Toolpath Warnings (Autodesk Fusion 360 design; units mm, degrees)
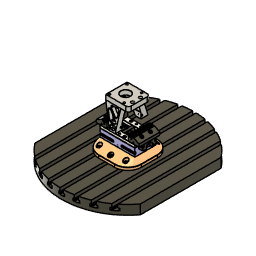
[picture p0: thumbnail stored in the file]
parameter "minJawOpening" = -31.6941 comment "Minimum Jaw Opening"
parameter "maxJawOpening" = 0 comment "Maximum Jaw Opening"
parameter "stockX" = 165.1 comment "Stock in X"
parameter "stockY" = 114.3 comment "Stock in Y"
parameter "stockZ" = 120.65 comment "Stock in Z"
base_feature "Base Feature1" OffsetX 0 OffsetY 0 OffsetZ 0 AngleZ 0
base_feature "Base Feature1"
base_feature "Base Feature1"
base_feature "Base Feature1"
base_feature "Base Feature1"
base_feature "Base Feature1"
base_feature "Base Feature1"
base_feature "Base Feature1"
base_feature "Base Feature1" OffsetX 0 OffsetY 0 OffsetZ 0 AngleZ 0 OffsetX 0 OffsetY 0 OffsetZ 0 AngleZ 0 OffsetX 0 OffsetY 0 OffsetZ 0 AngleZ 0 OffsetX 0 OffsetY 0 OffsetZ 0 AngleZ 0 OffsetX 0 OffsetY 0 OffsetZ 0 AngleZ 0
base_feature "Base Feature1" OffsetX 0 OffsetY 0 OffsetZ 0 AngleZ 0 OffsetX 0 OffsetY 0 OffsetZ 0 AngleZ 0 OffsetX 0 OffsetY 0 OffsetZ 0 AngleZ 0 OffsetX 0 OffsetY 0 OffsetZ 0 AngleZ 0 OffsetX 0 OffsetY 0 OffsetZ 0 AngleZ 0
base_feature "Base Feature1"
base_feature "Base Feature1"
base_feature "Base Feature1"
base_feature "Base Feature1"
as_built_joint "As-built1"
as_built_joint "As-built1"
as_built_joint "As-built1"
as_built_joint "As-built1"
as_built_joint "As-built1"
as_built_joint "As-built1"
joint "Assemble1" alignAngle 0 alignOffsetX 0 alignOffsetY 0 alignOffsetZ 0
as_built_joint "As-built3"
as_built_joint "As-built5"
as_built_joint "As-built6" OffsetX 0 OffsetY 0 OffsetZ 0 AngleZ 0
as_built_joint "As-built7" OffsetX 0 OffsetY 0 OffsetZ 0 AngleZ 0
work_plane "WorkPlane1" AlongDistance 0
joint_origin "JointOrigin1" OffsetX 0 OffsetY 0 OffsetZ 75.463 AngleZ 0
sketch "Sketch1" plane through (0, 0, 0) normal (0, 1, 0) x axis (1, 0, 0)
  line L1 (-15.24, -30.48) -> (-180.34, -30.48)
  line L2 (-15.24, 83.82) -> (-15.24, -30.48)
  line L3 (-180.34, 83.82) -> (-15.24, 83.82)
  line L4 (-180.34, -30.48) -> (-180.34, 83.82)
  point P2 (-180.34, -30.48)
  point P5 (-180.34, 83.82)
  point P3 (-15.24, -30.48)
  horizontal L1
  vertical L2
  horizontal L3
  vertical L4
  dimension "d111" distance P2 P5 = 114.3 (= "stockY")
  dimension "d112" distance P2 P3 = 165.1 (= "stockX")
  dimension "d318" OffsetX = 0
  dimension "d319" OffsetY = 0
  dimension "d320" OffsetZ = 0
  dimension "d321" AngleZ = 0
extrude "Extrude1" new body sketch "Sketch1" along normal blind 120.65 (= "stockZ")
joint_origin "JointOrigin1" OffsetX 0 OffsetY 0 OffsetZ 0 AngleZ 0
joint "Assemble2" alignAngle 0 alignOffsetX 0 alignOffsetY 0 alignOffsetZ 0
motion_link "MotionLink1" Value1 10.0076 Value2 10.0076
joint "Assemble3" alignAngle 180 alignOffsetX 0 alignOffsetY 0 alignOffsetZ 101.6 (= "stockY - 0.5 in")
base_feature "Base Feature1"
base_feature "Base Feature1"
joint "Assemble4" alignAngle 180 alignOffsetX 0 alignOffsetY 0 alignOffsetZ 0
joint "Assemble5" alignAngle 0 alignOffsetX 0 alignOffsetY 0 alignOffsetZ 0
base_feature "Base Feature1"
joint "Assemble6" alignAngle -90 alignOffsetX 0 alignOffsetY 0 alignOffsetZ 0
base_feature "Base Feature1"
joint_origin "JointOrigin1" OffsetX 0 named "d201_1" OffsetY 0 named "d202_1" OffsetZ 0 named "d203_1" AngleZ 0 named "d204_1"
base_feature "Base Feature1"
joint_origin "JointOrigin1" OffsetX 0 named "d201_2" OffsetY 0 named "d202_2" OffsetZ 0 named "d203_2" AngleZ 0 named "d204_2"
joint "Assemble7" alignAngle -90 alignOffsetX 0 alignOffsetY 0 alignOffsetZ 0
joint "Assemble8" alignAngle -90 alignOffsetX 0 alignOffsetY 0 alignOffsetZ 0
copy_paste "CutPaste1"
copy_paste "CutPaste2"
copy_paste "CutPaste1"
copy_paste "CutPaste2"
copy_paste "CutPaste3"
base_feature "Base Feature1"
joint_origin "JointOrigin1" OffsetX 0 named "d201_2_1" OffsetY 0 named "d202_2_1" OffsetZ 0 named "d203_2_1" AngleZ 0 named "d204_2_1"
joint_origin "JointOrigin2" OffsetX 0 named "d213_1" OffsetY 0 named "d214_1" OffsetZ 0 named "d215_1" AngleZ 0 named "d216_1"
base_feature "Base Feature1"
joint_origin "JointOrigin1" OffsetX 0 named "d201_3" OffsetY 0 named "d202_3" OffsetZ 0 named "d203_3" AngleZ 0 named "d204_3"
base_feature "Base Feature1"
joint_origin "JointOrigin1" OffsetX 0 named "d201_1_1" OffsetY 0 named "d202_1_1" OffsetZ 0 named "d203_1_1" AngleZ 0 named "d204_1_1"
joint_origin "JointOrigin2" OffsetX 0 named "d225_1" OffsetY 0 named "d226_1" OffsetZ 0 named "d227_1" AngleZ 0 named "d228_1"
joint "Assemble9" alignAngle 90 alignOffsetX 0 alignOffsetY 0 alignOffsetZ 0
joint "Assemble10" alignAngle 90 alignOffsetX 0 alignOffsetY 0 alignOffsetZ 0
joint "Assemble11" alignAngle 90 alignOffsetX 0 alignOffsetY 0 alignOffsetZ 0
copy_paste "CutPaste4"
copy_paste "CutPaste5"
copy_paste "CutPaste6"
base_feature "Base Feature1" OffsetX 0 OffsetY 0 OffsetZ 0 AngleZ 0 bodies "Table"
joint_origin "JointOrigin1" OffsetX 0 named "d149_1" OffsetY 0 named "d150_1" OffsetZ 0 named "d151_1" AngleZ 0 named "d152_1"
joint_origin "JointOrigin2" OffsetX 0 named "d153_1" OffsetY 0 named "d154_1" OffsetZ 0 named "d155_1" AngleZ 0 named "d156_1"
joint_origin "JointOrigin3" OffsetX 0 named "d157_1" OffsetY 0 named "d158_1" OffsetZ 0 named "d159_1" AngleZ 0 named "d160_1"
joint_origin "JointOrigin4" OffsetX 0 named "d161_1" OffsetY 0 named "d162_1" OffsetZ 0 named "d163_1" AngleZ 0 named "d164_1"
joint_origin "JointOrigin5" OffsetX 0 named "d165_1" OffsetY 0 named "d166_1" OffsetZ 0 named "d167_1" AngleZ 0 named "d168_1"
joint_origin "JointOrigin6" OffsetX 0 named "d169_1" OffsetY 0 named "d170_1" OffsetZ 0 named "d171_1" AngleZ 0 named "d172_1"
joint_origin "JointOrigin7" OffsetX 0 named "d173_1" OffsetY 0 named "d174_1" OffsetZ 0 named "d175_1" AngleZ 0 named "d176_1"
joint_origin "JointOrigin8" OffsetX 0 named "d177_1" OffsetY 0 named "d178_1" OffsetZ 0 named "d179_1" AngleZ 0 named "d180_1"
joint_origin "JointOrigin9" OffsetX 0 named "d181_1" OffsetY 0 named "d182_1" OffsetZ 0 named "d183_1" AngleZ 0 named "d184_1"
joint_origin "JointOrigin10" OffsetX 0 named "d185_1" OffsetY 0 named "d186_1" OffsetZ 0 named "d187_1" AngleZ 0 named "d188_1"
joint_origin "JointOrigin11" OffsetX 0 named "d189_1" OffsetY 0 named "d190_1" OffsetZ 0 named "d191_1" AngleZ 0 named "d192_1"
joint_origin "JointOrigin12" OffsetX 0 named "d193_1" OffsetY 0 named "d194_1" OffsetZ 0 named "d195_1" AngleZ 0 named "d196_1"
joint_origin "JointOrigin13" OffsetX 0 named "d197_1" OffsetY 0 named "d198_1" OffsetZ 0 named "d199_1" AngleZ 0 named "d200_1"
joint_origin "JointOrigin14" OffsetX 0 named "d201_4" OffsetY 0 named "d202_4" OffsetZ 0 named "d203_4" AngleZ 0 named "d204_4"
joint_origin "JointOrigin15" OffsetX 0 named "d205_1" OffsetY 0 named "d206_1" OffsetZ 0 named "d207_1" AngleZ 0 named "d208_1"
joint_origin "JointOrigin16" OffsetX 0 named "d209_1" OffsetY 0 named "d210_1" OffsetZ 0 named "d211_1" AngleZ 0 named "d212_1"
joint_origin "JointOrigin17" OffsetX 0 named "d213_2" OffsetY 0 named "d214_2" OffsetZ 0 named "d215_2" AngleZ 0 named "d216_2"
joint_origin "JointOrigin18" OffsetX 0 named "d217_1" OffsetY 0 named "d218_1" OffsetZ 0 named "d219_1" AngleZ 0 named "d220_1"
as_built_joint "As-built1"
joint "Assemble12" alignAngle 90 alignOffsetX 0 alignOffsetY 0 alignOffsetZ 38.1 (= "4 in - 2.5 in")
copy_paste "CutPaste1"
sketch "Sketch1" plane through (0, 0, 0) normal (0, -1, 0) x axis (1, 0, 0)
  line L1 (-50, 82.4998) -> (50, 82.4998)
  line L2 (-50, -82.4998) -> (-50, 82.4998)
  line L3 (50, -82.4998) -> (-50, -82.4998)
  line L4 (50, 82.4998) -> (50, -82.4998)
  line L5 (-50, -82.4998) -> (50, 82.4998)
  line L6 (50, -82.4998) -> (-50, 82.4998)
  point P6 (0, 0)
  point P1 (0, 0)
  point P2 (50, 82.4998)
  point P7 (50, 82.4998)
  perpendicular L1 L2
  parallel L1 L3
  parallel L2 L4
  horizontal L1
  coincident L5 P6
  coincident L6 P6
  coincident P1 P6
  coincident P2 P7
  dimension "d358" OffsetX = 0
  dimension "d359" OffsetY = 0
  dimension "d360" OffsetZ = 0
  dimension "d361" AngleZ = 0
extrude "Extrude1" new body sketch "Sketch1" profile of L1 L2 L3 L4 along normal blind 3.81
sketch "Sketch2" plane through (0, -38.1, 0) normal (0, 1, 0) x axis (-1, 0, 0)
  line L1 (-101.6, 101.6) -> (101.6, 101.6)
  line L2 (-101.6, -101.6) -> (-101.6, 101.6)
  line L3 (101.6, -101.6) -> (-101.6, -101.6)
  line L4 (101.6, 101.6) -> (101.6, -101.6)
  line L5 (-101.6, -101.6) -> (101.6, 101.6)
  line L6 (101.6, -101.6) -> (-101.6, 101.6)
  point P6 (0, 0)
  point P1 (0, 0)
  point P2 (101.6, 101.6)
  point P3 (-101.6, 101.6)
  perpendicular L1 L2
  parallel L1 L3
  parallel L2 L4
  horizontal L1
  coincident L5 P6
  coincident L6 P6
  coincident P1 P6
  equal L1 L4
  dimension "d287" distance P2 P3 = 203.2
extrude "Extrude2" new body sketch "Sketch2" profile of L1 L2 L3 L4 along normal blind 12.7
fillet "Fillet1" radius 63.5
fillet "Fillet2" radius 1.27
loft "Loft1"
sketch "Sketch3" plane through (0, -38.1, 0) normal (0, -1, 0) x axis (1, 0, 0)
  circle C1 centre (0, 0) radius 28.575
  point P1 (0, 0)
  point P2 (0, 0)
  coincident P1 P2
  dimension "d292" diameter C1 = 57.15
extrude "Extrude3" add sketch "Sketch3" along normal blind 6.35
as_built_joint "As-built8"
as_built_joint "As-built9"
sketch "Sketch2" plane through (0, 0, 0) normal (0, 0, 1) x axis (1, 0, 0)
  line L1 (482.6, 147.0957) -> (179.3748, 147.0957)
  line L2 (482.6, 58.1957) -> (482.6, 147.0957)
  line L3 (444.5, 58.1957) -> (482.6, 58.1957)
  line L4 (444.5, 80.4207) -> (444.5, 58.1957)
  line L5 (333.375, 80.4207) -> (444.5, 80.4207)
  line L6 (333.375, 110.2657) -> (333.375, 80.4207)
  line L7 (320.675, 110.2657) -> (333.375, 110.2657)
  line L8 (320.675, 115.3457) -> (320.675, 110.2657)
  line L9 (307.34, 115.3457) -> (320.675, 115.3457)
  line L10 (305.054, 124.7183) -> (307.34, 115.3457)
  line L11 (264.414, 124.7183) -> (305.054, 124.7183)
  line L12 (264.414, 128.4267) -> (264.414, 124.7183)
  line L13 (261.1628, 128.4267) -> (264.414, 128.4267)
  line L14 (261.1628, 124.7183) -> (261.1628, 128.4267)
  line L15 (255.5748, 124.7183) -> (261.1628, 124.7183)
  line L16 (255.5748, 127.1186) -> (255.5748, 124.7183)
  line L17 (217.4748, 127.1186) -> (255.5748, 127.1186)
  line L18 (217.4748, 140.7457) -> (217.4748, 127.1186)
  line L19 (179.3748, 140.7457) -> (217.4748, 140.7457)
  line L20 (179.3748, 147.0957) -> (179.3748, 140.7457)
  point P2 (179.3748, 147.0957)
  point P22 (179.3748, 147.0957)
  point P3 (482.6, 147.0957)
  point P4 (482.6, 58.1957)
  point P14 (264.414, 128.4267)
  point P15 (261.1628, 128.4267)
  point P5 (444.5, 58.1957)
  point P6 (444.5, 80.4207)
  point P7 (333.375, 80.4207)
  point P8 (333.375, 110.2657)
  point P9 (320.675, 110.2657)
  point P10 (320.675, 115.3457)
  point P11 (307.34, 115.3457)
  point P12 (305.054, 124.7183)
  point P13 (264.414, 124.7183)
  point P16 (261.1628, 124.7183)
  point P17 (255.5748, 124.7183)
  point P20 (217.4748, 140.7457)
  point P21 (179.3748, 140.7457)
  point P18 (255.5748, 127.1186)
  point P19 (217.4748, 127.1186)
  horizontal L1
  perpendicular L1 L2
  perpendicular L2 L3
  perpendicular L1 L4
  perpendicular L2 L5
  perpendicular L1 L6
  perpendicular L6 L7
  perpendicular L7 L8
  perpendicular L8 L9
  perpendicular L8 L11
  perpendicular L11 L12
  perpendicular L12 L13
  perpendicular L13 L14
  perpendicular L14 L15
  perpendicular L15 L16
  collinear L11 L15
  perpendicular L17 L18
  perpendicular L18 L19
  perpendicular L19 L20
  coincident P2 P22
  dimension "d295" distance P3 P4 = 88.9
  dimension "d296" distance L1 L5 = 66.675 (= "( 5.25 / 2 ) * 1 in")
  dimension "d297" distance L1 L7 = 36.83 (= "( 2.9 / 2 ) * 1 in")
  dimension "d298" distance L1 L9 = 31.75 (= "( 2.5 / 2 ) * 1 in")
  dimension "d299" distance L1 L11 = 22.3774 (= "( 1.762 / 2 ) * 1 in")
  dimension "d300" distance L1 L13 = 18.669 (= "( 1.47 / 2 ) * 1 in")
  dimension "d301" distance L1 L17 = 19.9771 (= "( 1.573 / 2 ) * 1 in")
  dimension "d302" distance P14 P15 = 3.2512
  dimension "d303" distance P4 P5 = 38.1
  dimension "d304" distance P6 P7 = 111.125
  dimension "d305" distance P8 P9 = 12.7
  dimension "d306" distance P10 P11 = 13.335
  dimension "d307" distance P11 P12 = 2.286
  dimension "d308" distance P12 P13 = 40.64
  dimension "d309" distance P16 P17 = 5.588
  dimension "d310" distance L1 L19 = 6.35
  dimension "d311" distance P20 P21 = 38.1
  dimension "d312" distance P18 P19 = 38.1
revolve "Revolve1" sketch "Sketch2" AlongAngle 360
component_from_bodies "Body->Comp"
joint "Assemble13" alignAngle 180 alignOffsetX 0 alignOffsetY -15.24 alignOffsetZ -12.7
copy_paste "CutPaste2"
copy_paste "CutPaste3"
sketch "Sketch4" plane through (0, -38.1, 0) normal (0, -1, 0) x axis (1, 0, 0)
  line L1 (-191.6377, 250) -> (191.6377, 250)
  line L2 (191.6377, -250) -> (-191.6377, -250)
  line L3 (310.1389, -55.126) -> (9.652, -55.126)
  line L4 (9.652, -70.874) -> (306.9232, -70.874)
  circle C1 centre (-73.025, 63) radius 6.6675
  circle C2 centre (73.025, 63) radius 6.6675
  circle C3 centre (82.55, 0) radius 6.6675
  circle C4 centre (-82.55, 0) radius 6.6675
  circle C5 centre (-73.025, -63) radius 6.6675
  circle C6 centre (73.025, -63) radius 6.6675
  arc A1 centre (0, 0) radius 315 clockwise from (191.6377, 250) to (191.6377, -250)
  arc A2 centre (0, 0) radius 315 clockwise from (-191.6377, -250) to (-191.6377, 250)
  circle C7 centre (59.8029, -16.0241) radius 6.7437
  circle C8 centre (-16.0241, -59.8029) radius 6.7437
  circle C9 centre (-43.7787, -43.7787) radius 6.7437
  circle C10 centre (-43.7787, 43.7787) radius 6.7437
  circle C11 centre (-16.0241, 59.8029) radius 6.7437
  circle C12 centre (59.8029, 16.0241) radius 6.7437
  circle C13 centre (0, 0) radius 0.4391
  arc A3 centre (-60.96, 63) radius 7.874 clockwise from (-60.96, 70.874) to (-60.96, 55.126)
  arc A4 centre (9.652, 63) radius 7.874 clockwise from (9.652, 55.126) to (9.652, 70.874)
  arc A5 centre (9.652, -63) radius 7.874 clockwise from (9.652, -70.874) to (9.652, -55.126)
  arc A6 centre (0, 0) radius 315 clockwise from (310.1389, -55.126) to (306.9232, -70.874)
  arc A7 centre (-60.96, -63) radius 7.874 clockwise from (-60.96, -55.126) to (-60.96, -70.874)
  arc A8 centre (-42.672, 0) radius 7.874 clockwise from (-42.672, 7.874) to (-42.672, -7.874)
  arc A9 centre (80.01, 0) radius 7.874 clockwise from (80.01, -7.874) to (80.01, 7.874)
  point P3 (73.025, 63)
  point P24 (9.652, 63)
  point P2 (-73.025, 63)
  point P7 (73.025, -63)
  point P27 (9.652, -63)
  point P6 (-73.025, -63)
  point P4 (82.55, 0)
  point P39 (80.01, 0)
  point P5 (-82.55, 0)
  point P36 (-42.672, 0)
  point P1 (0, 0)
  equal C5 C6
  equal C4 C5
  equal C1 C4
  equal C1 C2
  equal C2 C3
  horizontal P3 P24
  horizontal P2 P3
  horizontal P7 P27
  horizontal P6 P7
  vertical P2 P6
  vertical P3 P7
  horizontal P4 P39
  horizontal P5 P36
  dimension "d342" diameter C1 = 13.335
  dimension "d343" distance P1 P7 = 73.025
  dimension "d344" distance P1 P6 = 73.025 (= "d343")
  dimension "d346" distance P1 P5 = 82.55
  dimension "d347" distance P1 P4 = 82.55 (= "d346")
extrude "Extrude4" cut sketch "Sketch4" profile of C1 C2 C3 C4 C5 C6 A9 no distance stored
work_plane "WorkPlane1" AlongDistance -6.35
sketch "Sketch5" plane through (0, -31.75, 0) normal (0, -1, 0) x axis (1, 0, 0)
  circle C1 centre (73.025, 63) radius 9.8425
  circle C2 centre (73.025, 63) radius 6.6675
  circle C3 centre (82.55, 0) radius 9.8425
  circle C4 centre (73.025, -63) radius 9.8425
  circle C5 centre (-73.025, -63) radius 9.8425
  circle C6 centre (-82.55, 0) radius 9.8425
  circle C7 centre (-73.025, 63) radius 9.8425
  circle C8 centre (-73.025, 63) radius 6.6675
  circle C9 centre (-82.55, 0) radius 6.6675
  circle C10 centre (-73.025, -63) radius 6.6675
  circle C11 centre (73.025, -63) radius 6.6675
  circle C12 centre (82.55, 0) radius 6.6675
  concentric C1 C2
  equal C6 C7
  equal C5 C6
  equal C4 C5
  equal C3 C4
  equal C1 C3
  concentric C7 C8
  concentric C6 C9
  concentric C5 C10
  concentric C4 C11
  concentric C3 C12
  dimension "d349" diameter C1 = 19.685
extrude "Extrude5" cut sketch "Sketch5" no distance stored
chamfer "Chamfer1" distance 0.762
chamfer "Chamfer2" distance 0.762
base_feature "Base Feature1" OffsetX 0 OffsetY 0 OffsetZ 0 AngleZ 0
joint "Assemble14" alignAngle 0 alignOffsetX 0 alignOffsetY 0 alignOffsetZ 0
base_feature "Base Feature1" OffsetX 0 named "d354_1" OffsetY 0 named "d355_1" OffsetZ 0 named "d356_1" AngleZ 0 named "d357_1"
joint_origin "JointOrigin2" OffsetX 0 named "d366_1" OffsetY 0 named "d367_1" OffsetZ 0 named "d368_1" AngleZ 0 named "d369_1"
base_feature "Base Feature1" OffsetX 0 named "d354_2" OffsetY 0 named "d355_2" OffsetZ 0 named "d356_2" AngleZ 0 named "d357_2"
joint_origin "JointOrigin2" OffsetX 0 named "d366_2" OffsetY 0 named "d367_2" OffsetZ 0 named "d368_2" AngleZ 0 named "d369_2"
base_feature "Base Feature1" OffsetX 0 named "d354_3" OffsetY 0 named "d355_3" OffsetZ 0 named "d356_3" AngleZ 0 named "d357_3"
joint_origin "JointOrigin2" OffsetX 0 named "d366_3" OffsetY 0 named "d367_3" OffsetZ 0 named "d368_3" AngleZ 0 named "d369_3"
base_feature "Base Feature1" OffsetX 0 named "d354_4" OffsetY 0 named "d355_4" OffsetZ 0 named "d356_4" AngleZ 0 named "d357_4"
joint_origin "JointOrigin2" OffsetX 0 named "d366_4" OffsetY 0 named "d367_4" OffsetZ 0 named "d368_4" AngleZ 0 named "d369_4"
base_feature "Base Feature1" OffsetX 0 named "d354_5" OffsetY 0 named "d355_5" OffsetZ 0 named "d356_5" AngleZ 0 named "d357_5"
joint_origin "JointOrigin2" OffsetX 0 named "d366_5" OffsetY 0 named "d367_5" OffsetZ 0 named "d368_5" AngleZ 0 named "d369_5"
joint "Assemble15" alignAngle 0 alignOffsetX 0 alignOffsetY 0 alignOffsetZ 0
joint "Assemble16" alignAngle 0 alignOffsetX 0 alignOffsetY 0 alignOffsetZ 0
joint "Assemble17" alignAngle 0 alignOffsetX 0 alignOffsetY 0 alignOffsetZ 0
joint "Assemble18" alignAngle 0 alignOffsetX 0 alignOffsetY 0 alignOffsetZ 0
joint "Assemble19" alignAngle 0 alignOffsetX 0 alignOffsetY 0 alignOffsetZ 0
copy_paste "CutPaste4"
copy_paste "CutPaste5"
copy_paste "CutPaste6"
copy_paste "CutPaste7"
copy_paste "CutPaste8"
copy_paste "CutPaste9"
sketch "Sketch2" plane through (0, 0, 0) normal (0, -1, 0) x axis (1, 0, 0)
  line L1 (-50, 82.4998) -> (50, 82.4998)
  line L2 (-50, -82.4998) -> (-50, 82.4998)
  line L3 (50, -82.4998) -> (-50, -82.4998)
  line L4 (50, 82.4998) -> (50, -82.4998)
  line L5 (-50, -82.4998) -> (50, 82.4998)
  line L6 (50, -82.4998) -> (-50, 82.4998)
  point P6 (0, 0)
  point P1 (0, 0)
  point P2 (50, 82.4998)
  point P7 (50, 82.4998)
  perpendicular L1 L2
  parallel L1 L3
  parallel L2 L4
  horizontal L1
  coincident L5 P6
  coincident L6 P6
  coincident P1 P6
  coincident P2 P7
extrude "Extrude2" new body sketch "Sketch2" profile of L1 L2 L3 L4 along normal blind 2.54
fillet "Fillet2" radius 1.27
as_built_joint "As-built10"
remove_instance "RemoveInstance18"
base_feature "Base Feature1"
position "Position32"
joint "Assemble21" OffsetX 0 OffsetY 0 OffsetZ 0 AngleZ 0 alignAngle 180 alignOffsetX 0 alignOffsetY 0 alignOffsetZ -114.0572
as_built_joint "As-built12"
sketch "Side Containment" plane through (82.55, 0, 6.35) normal (1, 0, 0) x axis (0, 1, 0)
  line L1 (75.463, -63.5) -> (75.463, 50.8)
  line L2 (196.113, -63.5) -> (75.463, -63.5)
  line L3 (196.113, 50.8) -> (196.113, -63.5)
  line L4 (75.463, 50.8) -> (196.113, 50.8)
  line L5 (79.5905, 95.25) -> (231.9905, 95.25)
  line L6 (79.5905, 39.37) -> (79.5905, 95.25)
  line L7 (55.0926, 39.37) -> (79.5905, 39.37)
  line L8 (55.0926, -52.07) -> (55.0926, 39.37)
  line L9 (79.5905, -52.07) -> (55.0926, -52.07)
  line L10 (79.5905, -107.95) -> (79.5905, -52.07)
  line L11 (231.9905, -107.95) -> (79.5905, -107.95)
  line L12 (231.9905, 95.25) -> (231.9905, -107.95)
  line L13 (48.4465, 0) -> (48.4465, -12.7)
  line L14 (231.9905, -6.35) -> (48.4465, -6.35)
  line L15 (50.063, 44.45) -> (75.463, 44.45)
  line L16 (50.0126, 75.3878) -> (50.0126, -88.0878)
  line L17 (77.0505, 51.054) -> (77.0505, 63.246)
  point P16 (48.4465, -6.35)
  point P17 (231.9905, -6.35)
  point P6 (231.9905, 95.25)
  point P13 (231.9905, -107.95)
  point P7 (79.5905, 95.25)
  horizontal L5
  perpendicular L4 L6
  perpendicular L1 L7
  perpendicular L4 L8
  perpendicular L8 L9
  perpendicular L4 L10
  perpendicular L8 L11
  vertical L12
  midpoint L13 P16
  coincident L12 P17
  perpendicular L12 L14
  midpoint L12 P17
  equal L6 L10
  collinear L6 L10
  dimension "d464" distance L7 L15 = 5.08
  dimension "d465" distance L8 L16 = 5.08
  dimension "d466" distance L6 L17 = 2.54
  dimension "d467" distance P6 P13 = 203.2
  dimension "d468" distance P6 P7 = 152.4
base_feature "Base Feature1"
joint "Assemble22" OffsetX 0 OffsetY 0 OffsetZ 0 AngleZ 0 OffsetX 0 OffsetY 0 OffsetZ 0 AngleZ 0 alignAngle 0 alignOffsetX 0 alignOffsetY -6.35 alignOffsetZ 0
sketch "Sketch4" plane through (0, -38.1, 0) normal (0, 1, 0) x axis (-1, 0, 0)
  line L1 (245.7959, 197.001) -> (-245.7959, 197.001)
  line L2 (-191.6377, 250) -> (191.6377, 250)
  arc A1 centre (0, 0) radius 315 clockwise from (191.6377, 250) to (245.7959, 197.001)
  arc A2 centre (0, 0) radius 315 clockwise from (-245.7959, 197.001) to (-191.6377, 250)
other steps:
base_feature "Base Feature1" OffsetX 0 OffsetY 0 OffsetZ 0 AngleZ 0
create_component "CreateComponent1"
create_component "CreateComponent1"
create_component "CreateComponent2"
create_component "CreateComponent3"
create_component "CreateComponent4"
create_component "CreateComponent5"
create_component "CreateComponent6"
create_component "CreateComponent7"
create_component "CreateComponent2"
create_component "CreateComponent1"
create_component "CreateComponent2"
create_component "CreateComponent3"
create_component "CreateComponent1"
create_component "CreateComponent4"
create_component "CreateComponent1"
create_component "CreateComponent2"
create_component "CreateComponent5"
create_component "CreateComponent1"
create_component "CreateComponent6"
joint_origin "JointOrigin1" OffsetX 0 OffsetY 0 OffsetZ 0 AngleZ 0
joint_origin "JointOrigin1" OffsetX 0 OffsetY 0 OffsetZ 0 AngleZ 0
create_component "CreateComponent7"
joint_origin "JointOrigin6" OffsetX 0 OffsetY 0 OffsetZ 0 AngleZ 0
joint_origin "JointOrigin6" OffsetX 0 OffsetY 0 OffsetZ 0 AngleZ 0
create_component "CreateComponent8"
create_component "CreateComponent9"
joint_origin "JointOrigin1" OffsetX 0 OffsetY 0 OffsetZ 0 AngleZ 0
joint_origin "JointOrigin7" OffsetX 0 OffsetY 0 OffsetZ 0 AngleZ 0
joint_origin "JointOrigin1" OffsetX 0 OffsetY 0 OffsetZ 0 AngleZ 0
joint_origin "JointOrigin7" OffsetX 0 OffsetY 0 OffsetZ 0 AngleZ 0
create_component "CreateComponent10"
joint_origin "JointOrigin1" OffsetX 0 OffsetY 0 OffsetZ 0 AngleZ 0
joint_origin "JointOrigin8" OffsetX 0 OffsetY 0 OffsetZ 0 AngleZ 0
create_component "CreateComponent11"
create_component "CreateComponent12"
joint_origin "JointOrigin2" OffsetX 0 OffsetY 0 OffsetZ 0 AngleZ 0
joint_origin "JointOrigin9" OffsetX 0 OffsetY 0 OffsetZ 0 AngleZ 0
joint_origin "JointOrigin2" OffsetX 0 OffsetY 0 OffsetZ 0 AngleZ 0
joint_origin "JointOrigin10" OffsetX 0 OffsetY 0 OffsetZ 0 AngleZ 0
create_component "CreateComponent13"
remove_instance "RemoveInstance1"
remove_instance "RemoveInstance2"
create_component "CreateComponent14"
remove_instance "RemoveInstance3"
remove_instance "RemoveInstance4"
remove_instance "RemoveInstance5"
create_component "CreateComponent15"
create_component "CreateComponent16"
create_component "CreateComponent17"
joint_origin "JointOrigin2" OffsetX 0 OffsetY 0 OffsetZ 0 AngleZ 0
joint_origin "JointOrigin8" OffsetX 0 OffsetY 0 OffsetZ 0 AngleZ 0
joint_origin "JointOrigin3" OffsetX 0 OffsetY 0 OffsetZ 0 AngleZ 0
joint_origin "JointOrigin9" OffsetX 0 OffsetY 0 OffsetZ 0 AngleZ 0
joint_origin "JointOrigin3" OffsetX 0 OffsetY 0 OffsetZ 0 AngleZ 0
joint_origin "JointOrigin10" OffsetX 0 OffsetY 0 OffsetZ 0 AngleZ 0
remove_instance "RemoveInstance6"
remove_instance "RemoveInstance7"
remove_instance "RemoveInstance8"
create_component "CreateComponent18"
create_component "CreateComponent1"
create_component "CreateComponent19"
remove_instance "RemoveInstance9"
create_component "CreateComponent20"
create_component "CreateComponent21"
remove_body "RemoveBody1"
joint_origin "JointOrigin3" OffsetX 0 OffsetY 0 OffsetZ 0 AngleZ 0
joint_origin "JointOrigin20" OffsetX 0 OffsetY 0 OffsetZ 0 AngleZ 0
joint_origin "JointOrigin2" OffsetX 0 OffsetY 0 OffsetZ 0 AngleZ 0
joint_origin "JointOrigin3" OffsetX 0 OffsetY 0 OffsetZ 0 AngleZ 0
remove_instance "RemoveInstance10"
remove_instance "RemoveInstance11"
create_component "CreateComponent22"
joint_origin "JointOrigin2" OffsetX 0 OffsetY 0 OffsetZ 0 AngleZ 0
joint_origin "JointOrigin2" OffsetX 0 OffsetY 0 OffsetZ 0 AngleZ 0
create_component "CreateComponent23"
create_component "CreateComponent24"
create_component "CreateComponent25"
create_component "CreateComponent26"
create_component "CreateComponent27"
joint_origin "JointOrigin3" OffsetX 0 OffsetY 0 OffsetZ 0 AngleZ 0
joint_origin "JointOrigin3" OffsetX 0 OffsetY 0 OffsetZ 0 AngleZ 0
joint_origin "JointOrigin3" OffsetX 0 OffsetY 0 OffsetZ 0 AngleZ 0
joint_origin "JointOrigin4" OffsetX 0 OffsetY 0 OffsetZ 0 AngleZ 0
joint_origin "JointOrigin3" OffsetX 0 OffsetY 0 OffsetZ 0 AngleZ 0
joint_origin "JointOrigin5" OffsetX 0 OffsetY 0 OffsetZ 0 AngleZ 0
joint_origin "JointOrigin3" OffsetX 0 OffsetY 0 OffsetZ 0 AngleZ 0
joint_origin "JointOrigin6" OffsetX 0 OffsetY 0 OffsetZ 0 AngleZ 0
joint_origin "JointOrigin3" OffsetX 0 OffsetY 0 OffsetZ 0 AngleZ 0
joint_origin "JointOrigin7" OffsetX 0 OffsetY 0 OffsetZ 0 AngleZ 0
remove_instance "RemoveInstance12"
remove_instance "RemoveInstance13"
remove_instance "RemoveInstance14"
remove_instance "RemoveInstance15"
remove_instance "RemoveInstance16"
remove_instance "RemoveInstance17"
create_component "CreateComponent29"
joint_origin "JointOrigin4" OffsetX 0 OffsetY 0 OffsetZ 0 AngleZ 0
create_component "CreateComponent30"
create_component "CreateComponent31"
named bodies: "Table"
